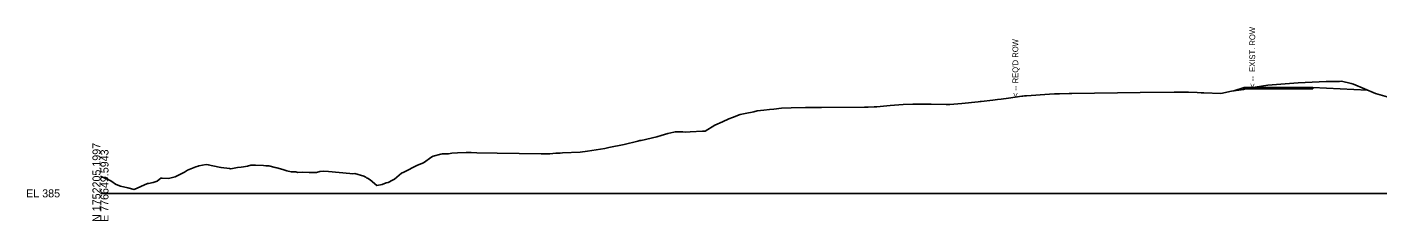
# Model space of a CAD drawing. Extents: x 776426 to 854588, y 1736205 to 1756790.
# Drawn here: x 805845.1 to 806317.6, y 1751205.1 to 1751273.1 of the extents above; entities that cross this region are included whole.
import ezdxf

# ---------------------------------------------------------------- set-up
doc = ezdxf.new("R2010")
doc.units = 0
for name, color, linetype in [('DTM CONTOURS_MAJOR_TX', 7, 'Continuous'), ('DTM_X_FLOW_ARROWS', 7, 'Continuous'), ('XS_P_DR_GRAVEL', 7, 'Continuous'), ('XS_P_GROUND', 7, 'Continuous'), ('XS_P_ROW', 7, 'Continuous'), ('XS_X_ROW', 7, 'Continuous')]:
    doc.layers.add(name, color=color, linetype=linetype)

msp = doc.modelspace()

# ---------------------------------------------------------------- linework, layer by layer
at = {"layer": 'DTM CONTOURS_MAJOR_TX'}
msp.add_line((805870.79, 1751214.76), (806370.79, 1751214.76), dxfattribs=at)
at = {"layer": 'DTM_X_FLOW_ARROWS'}
msp.add_lwpolyline([(805870.79, 1751220.67), (805871.05, 1751220.69), (805872.34, 1751220.07), (805874.21, 1751219.27), (805875.12, 1751218.65), (805875.75, 1751218.24), (805876.33, 1751217.85), (805877.79, 1751217.24), (805880.39, 1751216.65), (805882.56, 1751216.16), (805887.23, 1751218.18), (805887.62, 1751218.28), (805889.26, 1751218.56), (805890.59, 1751219.08), (805891.29, 1751219.68), (805891.93, 1751220.05), (805892.38, 1751220.13), (805894.53, 1751220.02), (805896.87, 1751220.55), (805900.16, 1751222.2), (805901.21, 1751222.85), (805904.11, 1751224.12), (805904.93, 1751224.33), (805905.25, 1751224.41), (805907.78, 1751224.88), (805908.46, 1751224.77), (805912.34, 1751223.94), (805912.97, 1751223.83), (805915.94, 1751223.45), (805916.31, 1751223.38), (805916.97, 1751223.49), (805918.73, 1751223.85), (805920.02, 1751223.94), (805920.78, 1751224.04), (805922.24, 1751224.35), (805923.42, 1751224.6), (805924.31, 1751224.66), (805925.02, 1751224.67), (805927.78, 1751224.48), (805928.59, 1751224.45), (805929.65, 1751224.36), (805931.85, 1751223.78), (805932.47, 1751223.73), (805934.56, 1751223.11), (805935.97, 1751222.65), (805937.53, 1751222.27), (805939.09, 1751222.31), (805939.78, 1751222.02), (805941.33, 1751222.15), (805943.82, 1751222.02), (805944.37, 1751222.09), (805946.38, 1751222.13), (805947.51, 1751222.4), (805948.81, 1751222.51), (805950.51, 1751222.38), (805957.97, 1751221.68), (805959.1, 1751221.61), (805959.8, 1751221.7), (805962.93, 1751220.77), (805963.66, 1751220.41), (805964.01, 1751220.04), (805964.23, 1751220.09), (805965.11, 1751219.46), (805967.48, 1751217.58), (805969.34, 1751217.85), (805970.73, 1751218.45), (805971.47, 1751218.62), (805972.95, 1751219.4), (805973.65, 1751219.74), (805976.03, 1751221.79), (805976.92, 1751222.19), (805981.68, 1751224.69), (805983.77, 1751225.45), (805986.73, 1751227.53), (805987.17, 1751227.85), (805989.79, 1751228.54), (805990.33, 1751228.57), (805992.56, 1751228.66), (805993.73, 1751228.87), (805995.63, 1751228.99), (805998.7, 1751229.08), (806000.5, 1751229.04), (806002.4, 1751229.02), (806009.49, 1751228.81), (806024.93, 1751228.67), (806027.93, 1751228.64), (806030.04, 1751228.86), (806031.06, 1751228.86), (806031.59, 1751228.86), (806032.44, 1751228.95), (806038.62, 1751229.23), (806041.1, 1751229.59), (806047.25, 1751230.54), (806048.59, 1751230.82), (806053.98, 1751231.91), (806058.75, 1751233.06), (806059.5, 1751233.26), (806059.94, 1751233.35), (806065.37, 1751234.53), (806066.91, 1751235.07), (806069.25, 1751235.79), (806071.35, 1751236.22), (806071.79, 1751236.32), (806074.46, 1751236.29), (806075.54, 1751236.25), (806077.05, 1751236.31), (806081.4, 1751236.58), (806082.34, 1751236.6), (806085.63, 1751238.69), (806088.31, 1751239.89), (806090.63, 1751240.94), (806091.82, 1751241.41), (806094.57, 1751242.41), (806096.32, 1751242.81), (806099.27, 1751243.37), (806100.5, 1751243.65), (806102.77, 1751243.94), (806104.82, 1751244.14), (806106.3, 1751244.22), (806108.97, 1751244.57), (806112.38, 1751244.71), (806117.37, 1751244.86), (806118.31, 1751244.87), (806119.17, 1751244.87), (806120.05, 1751244.88), (806123.01, 1751244.88), (806137.98, 1751244.99), (806139.31, 1751244.97), (806141.44, 1751245.08), (806141.98, 1751245.1), (806142.37, 1751245.13), (806147.05, 1751245.61), (806151.5, 1751245.94), (806154.96, 1751245.98), (806155.31, 1751245.98), (806155.71, 1751246), (806157.63, 1751246.01), (806158.08, 1751246), (806159.78, 1751246.03), (806160.14, 1751246.05), (806161.34, 1751246.04), (806166.65, 1751245.92), (806167.85, 1751245.89), (806172.06, 1751246.21), (806177.76, 1751246.87), (806178.52, 1751246.97), (806178.85, 1751247.01), (806182.96, 1751247.48), (806184.6, 1751247.63), (806185.82, 1751247.78), (806188.37, 1751248.12), (806193, 1751248.8), (806193.37, 1751248.87), (806194.01, 1751248.94), (806194.72, 1751248.99), (806202.76, 1751249.53), (806204.48, 1751249.63), (806206.18, 1751249.69), (806209.64, 1751249.78), (806209.99, 1751249.8), (806210.57, 1751249.8), (806234.48, 1751250.06), (806246.34, 1751250.18), (806249.19, 1751250.21), (806251.41, 1751250.22), (806254.39, 1751250.12), (806255.78, 1751250.05), (806256.73, 1751250.04), (806262.64, 1751249.8), (806266.42, 1751250.61), (806270.59, 1751251.22), (806270.93, 1751251.28), (806271.37, 1751251.36), (806274.72, 1751251.96), (806279.09, 1751252.68), (806289.71, 1751253.47), (806297.11, 1751253.82), (806299.46, 1751253.94), (806302.3, 1751253.99), (806302.98, 1751253.99), (806303.35, 1751253.99), (806304.12, 1751254.02), (806304.86, 1751254.06), (806308.2, 1751253.23), (806309.02, 1751253.03), (806316.72, 1751249.76), (806321.7, 1751248.35)], dxfattribs=at)
at = {"layer": 'XS_P_DR_GRAVEL'}
for points in [[(806282.79, 1751251.91), (806282.79, 1751251.41), (806270.79, 1751251.41), (806270.79, 1751251.91), (806282.79, 1751251.91)], [(806282.79, 1751251.91), (806282.79, 1751251.41), (806294.79, 1751251.41), (806294.79, 1751251.91), (806282.79, 1751251.91)]]:
    msp.add_lwpolyline(points, dxfattribs=at)
at = {"layer": 'XS_P_GROUND'}
for points in [[(806267.24, 1751250.73), (806270.79, 1751251.91)], [(806294.79, 1751251.91), (806313.91, 1751250.96)]]:
    msp.add_lwpolyline(points, dxfattribs=at)

# ---------------------------------------------------------------- texts
at = {"layer": 'DTM CONTOURS_MAJOR_TX'}
for s, p in [('N 1752205.1997', (805870.79, 1751204.76)), ('E 776649.5943', (805873.59, 1751204.76))]:
    msp.add_text(s, height=2.8, rotation=90, dxfattribs=at).set_placement(p)
msp.add_text('EL 385', height=2.8, dxfattribs=at).set_placement((805844.79, 1751213.36))
at = {"layer": 'XS_P_ROW'}
msp.add_text("< -- REQ'D ROW", height=2, rotation=90, dxfattribs=at).set_placement((806191.79, 1751248.48))
at = {"layer": 'XS_X_ROW'}
msp.add_text('< --  EXIST. ROW', height=2, rotation=90, dxfattribs=at).set_placement((806274.67, 1751251.77))

doc.saveas('drawing.dxf')
